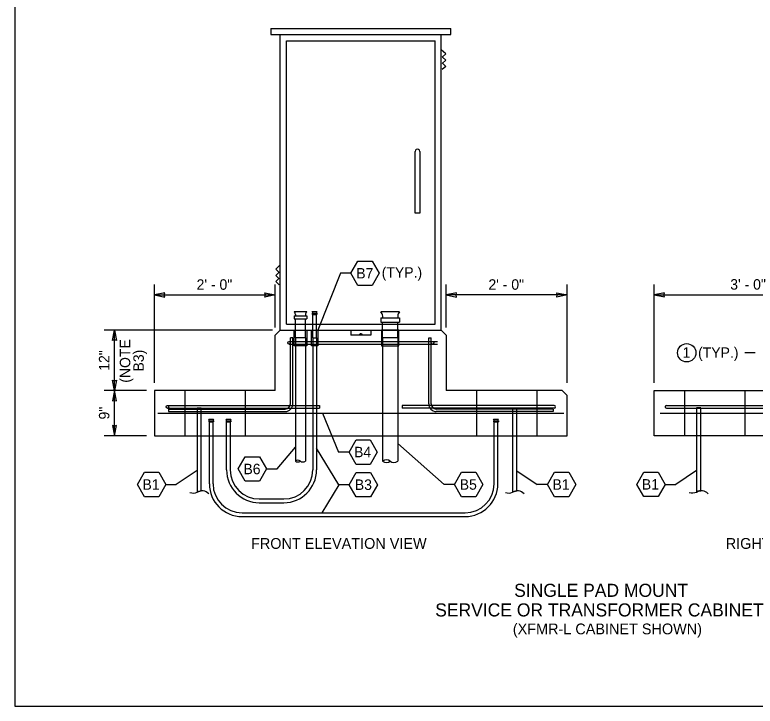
# Model space of a CAD drawing. Extents: x 99862 to 103151, y 100000 to 117076.
# Drawn here: x 99862 to 100994, y 106000 to 107057 of the extents above; entities that cross this region are included whole.
import ezdxf

# ---------------------------------------------------------------- set-up
doc = ezdxf.new("R2010")
doc.units = 0
for name, color, linetype in [('Default', 7, 'Continuous'), ('Level 1', 7, 'Continuous'), ('Level 11', 7, 'Continuous'), ('Level 15', 7, 'Continuous'), ('Level 20', 7, 'Continuous'), ('Level 40', 7, 'Continuous'), ('Level 60', 7, 'Continuous'), ('Level 9', 7, 'Continuous')]:
    doc.layers.add(name, color=color, linetype=linetype)

msp = doc.modelspace()

# ---------------------------------------------------------------- linework, layer by layer
at = {"layer": 'Default'}
for p, q in [((100281.4, 106557.2), (100508.4, 106557.2)), ((100283.4, 106461.6), (100283.4, 106562.9)), ((100287.2, 106562.9), (100283.4, 106562.9)), ((100287.2, 106461.6), (100287.2, 106562.9)), ((100495, 106461.6), (100495, 106562.9)), ((100495, 106562.9), (100498.8, 106562.9)), ((100498.8, 106461.6), (100498.8, 106562.9)), ((100281.4, 106553.3), (100508.4, 106553.3)), ((100095.4, 106459.1), (100327.9, 106459.1)), ((100095.4, 106455.3), (100327.9, 106455.3)), ((100327.9, 106459.1), (100327.9, 106455.3)), ((100454.2, 106459.1), (100454.2, 106455.3)), ((100686.8, 106459.1), (100454.2, 106459.1)), ((100686.8, 106455.3), (100454.2, 106455.3)), ((100858.4, 106459.1), (101091, 106459.1)), ((100858.4, 106455.3), (101091, 106455.3)), ((100096.8, 106453.9), (100096.8, 106450.1)), ((100096.8, 106453.9), (100275.7, 106453.9)), ((100096.8, 106450.1), (100275.7, 106450.1)), ((100685.4, 106453.9), (100506.5, 106453.9)), ((100685.4, 106450.1), (100506.5, 106450.1)), ((100685.4, 106453.9), (100685.4, 106450.1))]:
    msp.add_line(p, q, dxfattribs=at)
for centre, radius in [((100391.1, 106568.2), 1.44), ((100281.4, 106555.2), 1.92), ((100500.7, 106555.2), 1.92), ((100095.4, 106457.2), 1.92)]:
    msp.add_circle(centre, radius, dxfattribs=at)
for centre, radius, start, end in [((100275.7, 106461.6), 11.5, 270, 0), ((100275.7, 106461.6), 7.7, 270, 0), ((100506.5, 106461.6), 11.5, 180, 270), ((100506.5, 106461.6), 7.7, 180, 270), ((100686.8, 106457.2), 1.92, 270, 90), ((100858.4, 106457.2), 1.92, 90, 270.01)]:
    msp.add_arc(centre, radius, start, end, dxfattribs=at)
at = {"layer": 'Level 1'}
for p, q in [((100289.2, 106602.8), (100308.4, 106602.8)), ((100316.9, 106602.8), (100324.1, 106602.8)), ((100421.6, 106602.8), (100450.5, 106602.8)), ((100289.2, 106596.4), (100289.2, 106591.9)), ((100289.2, 106596.4), (100308.4, 106596.4)), ((100289.2, 106591.9), (100308.4, 106591.9)), ((100291.1, 106598.2), (100291.1, 106596.4)), ((100291.1, 106562.6), (100291.1, 106591.9)), ((100306.5, 106598.2), (100306.5, 106596.4)), ((100306.5, 106562.6), (100306.5, 106591.9)), ((100308.4, 106596.4), (100308.4, 106591.9)), ((100316.9, 106600.4), (100316.9, 106598.7)), ((100316.9, 106600.4), (100324.1, 106600.4)), ((100316.9, 106598.7), (100324.1, 106598.7)), ((100317.6, 106601.1), (100317.6, 106600.4)), ((100317.6, 106562.6), (100317.6, 106598.7)), ((100323.4, 106601.1), (100323.4, 106600.4)), ((100323.4, 106562.6), (100323.4, 106598.7)), ((100324.1, 106600.4), (100324.1, 106598.7)), ((100421.6, 106593.3), (100421.6, 106586.5)), ((100421.6, 106593.3), (100450.5, 106593.3)), ((100424.5, 106595.9), (100424.5, 106593.3)), ((100447.6, 106595.9), (100447.6, 106593.3)), ((100450.5, 106593.3), (100450.5, 106586.5)), ((100421.6, 106586.5), (100450.5, 106586.5)), ((100424.5, 106562.6), (100424.5, 106586.5)), ((100447.6, 106562.6), (100447.6, 106586.5)), ((100306.5, 106562.6), (100291.1, 106562.6)), ((100291.1, 106562.6), (100291.1, 106374.3)), ((100306.5, 106562.6), (100306.5, 106374.3)), ((100317.6, 106562.6), (100323.4, 106562.6)), ((100317.6, 106562.6), (100317.6, 106360.7)), ((100323.4, 106562.6), (100323.4, 106360.7)), ((100424.5, 106562.6), (100424.5, 106374.3)), ((100447.6, 106562.6), (100424.5, 106562.6)), ((100447.6, 106562.6), (100447.6, 106374.3)), ((100158.8, 106438.3), (100166, 106438.3)), ((100158.8, 106436), (100158.8, 106434.3)), ((100158.8, 106436), (100166, 106436)), ((100158.8, 106434.3), (100166, 106434.3)), ((100159.5, 106436.6), (100159.5, 106436)), ((100159.5, 106339.5), (100159.5, 106434.3)), ((100165.3, 106436.6), (100165.3, 106436)), ((100165.3, 106339.5), (100165.3, 106434.3)), ((100166, 106436), (100166, 106434.3)), ((100185.2, 106438.3), (100192.4, 106438.3)), ((100185.2, 106436), (100185.2, 106434.3)), ((100185.2, 106436), (100192.4, 106436)), ((100185.2, 106434.3), (100192.4, 106434.3)), ((100185.9, 106436.6), (100185.9, 106436)), ((100185.9, 106360.7), (100185.9, 106434.3)), ((100191.7, 106436.6), (100191.7, 106436)), ((100191.7, 106360.7), (100191.7, 106434.3)), ((100192.4, 106436), (100192.4, 106434.3)), ((100594.3, 106438.3), (100601.5, 106438.3)), ((100594.3, 106436), (100594.3, 106434.3)), ((100594.3, 106436), (100601.5, 106436)), ((100594.3, 106434.3), (100601.5, 106434.3)), ((100595, 106436.6), (100595, 106436)), ((100595, 106338), (100595, 106434.3)), ((100600.7, 106436.6), (100600.7, 106436)), ((100600.7, 106337.9), (100600.7, 106434.3)), ((100601.5, 106436), (100601.5, 106434.3)), ((100235.9, 106316.4), (100273.4, 106316.4)), ((100235.9, 106310.7), (100273.4, 106310.7)), ((100209.5, 106295.3), (100550.7, 106295.3)), ((100209.5, 106289.5), (100550.7, 106289.5))]:
    msp.add_line(p, q, dxfattribs=at)
for points in [[(99862, 105999.5), (103151, 105999.5), (103151, 108075.5), (99862, 108075.5)], [(100308.4, 106550.6), (100289.2, 106550.6), (100289.2, 106574.5), (100308.4, 106574.5)], [(100315.7, 106574.5), (100325.3, 106574.5), (100325.3, 106550.6), (100315.7, 106550.6)], [(100422.6, 106550.6), (100449.5, 106550.6), (100449.5, 106574.5), (100422.6, 106574.5)], [(100141, 106455.3), (100141, 106326.8), (100143.2, 106327.9), (100145.2, 106328.5), (100147.2, 106328.8), (100147.2, 106455.3)], [(100623.3, 106455.3), (100623.3, 106326.8), (100625.5, 106327.9), (100627.5, 106328.5), (100629.5, 106328.8), (100629.6, 106455.3)], [(100904.7, 106455.5), (100904.7, 106327), (100906.9, 106328.1), (100908.9, 106328.7), (100910.9, 106329), (100910.9, 106455.5)]]:
    msp.add_lwpolyline(points, close=True, dxfattribs=at)
for centre, radius, start, end in [((100284.8, 106598.2), 6.32, 0, 45.9402), ((100312.8, 106598.2), 6.32, 134.0598, 180), ((100315.3, 106601.1), 2.37, 0, 45.9402), ((100325.8, 106601.1), 2.37, 134.0598, 180), ((100415.1, 106595.9), 9.47, 0, 45.9402), ((100457.1, 106595.9), 9.47, 134.0598, 180), ((100157.1, 106436.6), 2.37, 0, 45.9402), ((100167.7, 106436.6), 2.37, 134.0598, 180), ((100183.5, 106436.6), 2.37, 0, 45.9402), ((100194, 106436.6), 2.37, 134.0598, 180), ((100592.6, 106436.6), 2.37, 0, 45.9402), ((100603.1, 106436.6), 2.37, 134.0598, 180), ((100430.3, 106367.2), 9.14, 50.8329, 129.1671), ((100294.9, 106369.6), 6.09, 50.8329, 129.1671), ((100294.9, 106379), 6.09, 230.8329, 309.1671), ((100302.6, 106379), 6.09, 230.8329, 309.1671), ((100430.3, 106381.4), 9.14, 230.8329, 309.1671), ((100441.8, 106381.4), 9.14, 230.8329, 309.1671), ((100235.9, 106360.7), 50, 180, 270), ((100235.9, 106360.7), 44.3, 180, 270), ((100273.4, 106360.7), 44.3, 270, 0), ((100273.4, 106360.7), 50, 270, 0), ((100209.5, 106339.5), 50, 180, 270), ((100209.5, 106339.5), 44.3, 180, 270), ((100550.7, 106339.5), 44.3, 270, 0), ((100550.7, 106339.5), 50, 270, 0), ((100134.6, 106340), 14.6, 250.7571, 295.3506), ((100148.2, 106314.7), 14.1, 42.3778, 121.1813), ((100617, 106340), 14.6, 250.7571, 295.3506), ((100630.5, 106314.7), 14.1, 42.3778, 121.1813), ((100898.3, 106340.2), 14.6, 250.7571, 295.3506), ((100911.9, 106314.9), 14.1, 42.3778, 121.1813)]:
    msp.add_arc(centre, radius, start, end, dxfattribs=at)
at = {"layer": 'Level 11'}
for p, q in [((100375.7, 106574.5), (100375.7, 106566.8)), ((100406.5, 106574.5), (100406.5, 106566.8)), ((100406.5, 106566.8), (100375.7, 106566.8)), ((100121.8, 106482.1), (100121.8, 106412.9)), ((100214.1, 106482.1), (100214.1, 106412.9)), ((100568.1, 106482.1), (100568.1, 106412.9)), ((100660.4, 106482.1), (100660.4, 106412.9)), ((100885.9, 106482.3), (100885.9, 106413.1)), ((100978.3, 106482.3), (100978.3, 106413.1))]:
    msp.add_line(p, q, dxfattribs=at)
for points in [[(100260.3, 106482.1), (100260.3, 106566.8), (100268, 106574.5)], [(100268, 106574.5), (100514.2, 106574.5)], [(100514.2, 106574.5), (100521.9, 106566.8), (100521.9, 106482.1)], [(100075.6, 106482.1), (100075.6, 106412.9)], [(100260.3, 106482.1), (100075.6, 106482.1)], [(100698.9, 106482.1), (100521.9, 106482.1)], [(100706.6, 106412.9), (100706.6, 106474.4), (100698.9, 106482.1)], [(100839.7, 106482.3), (101128.3, 106482.3)], [(100839.7, 106413.1), (100839.7, 106482.3)], [(100075.6, 106412.9), (100706.6, 106412.9)], [(101363, 106413.1), (100839.7, 106413.1)]]:
    msp.add_lwpolyline(points, dxfattribs=at)
at = {"layer": 'Level 15'}
for p, q in [((100359.9, 106661.5), (100325.3, 106574.5)), ((100375.9, 106661.5), (100359.9, 106661.5)), ((100075.6, 106494.1), (100075.6, 106644.3)), ((100260.3, 106578.8), (100260.3, 106644.3)), ((100521.9, 106578.8), (100521.9, 106644.3)), ((100706.6, 106494.1), (100706.6, 106644.3)), ((100839.7, 106494.1), (100839.7, 106644.5)), ((100075.6, 106628.3), (100260.3, 106628.3)), ((100706.6, 106628.3), (100521.9, 106628.3)), ((100839.7, 106628.5), (101128.3, 106628.5)), ((100256, 106574.5), (99998.6, 106574.5)), ((100014.6, 106482.1), (100014.6, 106574.5)), ((100978.2, 106540.2), (100994.2, 106540.2)), ((100063.6, 106482.1), (99998.6, 106482.1)), ((100014.6, 106412.9), (100014.6, 106482.1)), ((100332.5, 106447.4), (100357.1, 106388)), ((100063.6, 106412.9), (99998.6, 106412.9)), ((100518.5, 106338.5), (100447.6, 106401)), ((100263, 106362.2), (100291.1, 106395.6)), ((100357.4, 106338.2), (100323.4, 106394.2)), ((100373.1, 106388), (100357.1, 106388)), ((100141, 106359.9), (100109, 106338.5)), ((100247, 106362.2), (100263, 106362.2)), ((100629.5, 106359.4), (100660.7, 106338.5)), ((100904.7, 106360.1), (100872.7, 106338.7)), ((100093, 106338.5), (100109, 106338.5)), ((100357.4, 106338.2), (100331.5, 106295.3)), ((100373.4, 106338.2), (100357.4, 106338.2)), ((100534.5, 106338.5), (100518.5, 106338.5)), ((100676.7, 106338.5), (100660.7, 106338.5)), ((100856.7, 106338.7), (100872.7, 106338.7))]:
    msp.add_line(p, q, dxfattribs=at)
for points in [[(100075.6, 106628.3), (100091.3, 106625.2), (100090.6, 106628.3), (100091.3, 106631.4)], [(100260.3, 106628.3), (100244.5, 106625.2), (100245.3, 106628.3), (100244.5, 106631.4)], [(100521.9, 106628.3), (100537.6, 106625.2), (100536.9, 106628.3), (100537.6, 106631.4)], [(100706.6, 106628.3), (100690.9, 106625.2), (100691.6, 106628.3), (100690.9, 106631.4)], [(100839.7, 106628.5), (100855.5, 106625.4), (100854.7, 106628.5), (100855.5, 106631.6)], [(100014.6, 106574.5), (100017.7, 106558.8), (100014.6, 106559.5), (100011.5, 106558.8)], [(100014.6, 106482.1), (100011.5, 106497.9), (100014.6, 106497.1), (100017.7, 106497.9)], [(100014.6, 106482.1), (100011.5, 106466.4), (100014.6, 106467.1), (100017.7, 106466.4)], [(100014.6, 106412.9), (100017.7, 106428.6), (100014.6, 106427.9), (100011.5, 106428.6)]]:
    msp.add_lwpolyline(points, close=True, dxfattribs=at)
at = {"layer": 'Level 20'}
for points in [[(100375.9, 106661.5), (100386.7, 106680.2), (100408.3, 106680.2), (100419.1, 106661.5), (100408.3, 106642.7), (100386.7, 106642.7), (100375.9, 106661.5)], [(100373.1, 106388), (100384, 106406.8), (100405.6, 106406.8), (100416.4, 106388), (100405.6, 106369.3), (100384, 106369.3), (100373.1, 106388)], [(100203.7, 106362.2), (100214.5, 106380.9), (100236.2, 106380.9), (100247, 106362.2), (100236.2, 106343.4), (100214.5, 106343.4), (100203.7, 106362.2)], [(100049.7, 106338.5), (100060.5, 106357.2), (100082.2, 106357.2), (100093, 106338.5), (100082.2, 106319.7), (100060.5, 106319.7), (100049.7, 106338.5)], [(100373.4, 106338.2), (100384.2, 106356.9), (100405.9, 106356.9), (100416.7, 106338.2), (100405.9, 106319.4), (100384.2, 106319.4), (100373.4, 106338.2)], [(100534.5, 106338.5), (100545.3, 106357.2), (100567, 106357.2), (100577.8, 106338.5), (100567, 106319.7), (100545.3, 106319.7), (100534.5, 106338.5)], [(100676.7, 106338.5), (100687.5, 106357.2), (100709.2, 106357.2), (100720, 106338.5), (100709.2, 106319.7), (100687.5, 106319.7), (100676.7, 106338.5)], [(100813.4, 106338.7), (100824.2, 106357.4), (100845.9, 106357.4), (100856.7, 106338.7), (100845.9, 106319.9), (100824.2, 106319.9), (100813.4, 106338.7)]]:
    msp.add_lwpolyline(points, dxfattribs=at)
msp.add_circle((100889.6, 106539.9), 14, dxfattribs=at)
at = {"layer": 'Level 40'}
for p, q in [((100080.7, 106447.5), (100701.5, 106447.5)), ((100848.7, 106447.7), (101354, 106447.7))]:
    msp.add_line(p, q, dxfattribs=at)
at = {"layer": 'Level 60'}
msp.add_line((99862, 105999.5), (99862, 105999.5), dxfattribs=at)
at = {"layer": 'Level 9'}
for p, q in [((100253.5, 107036), (100528.6, 107036)), ((100253.5, 107036), (100253.5, 107026.5)), ((100528.6, 107026.5), (100528.6, 107036)), ((100253.5, 107026.5), (100268, 107026.5)), ((100268, 106574.5), (100268, 107026.5)), ((100268, 107026.5), (100528.6, 107026.5)), ((100514.2, 106574.5), (100514.2, 107026.5)), ((100277.6, 106583.9), (100277.6, 107017.1)), ((100277.6, 107017.1), (100504.6, 107017.1)), ((100504.6, 106583.9), (100504.6, 107017.1)), ((100521, 106996.8), (100514.2, 107003.4)), ((100521, 106996.8), (100515.8, 106991.8)), ((100521, 106987.3), (100515.8, 106982.3)), ((100521, 106987.3), (100516.1, 106992.1)), ((100521, 106977.9), (100515.8, 106972.9)), ((100521, 106977.9), (100516.1, 106982.6)), ((100474.1, 106843.2), (100474.1, 106847.9)), ((100474.1, 106753.6), (100474.1, 106843.2)), ((100481.3, 106847.9), (100481.3, 106843.2)), ((100481.3, 106843.2), (100481.3, 106753.6)), ((100481.3, 106753.6), (100474.1, 106753.6)), ((100261.2, 106667.6), (100268, 106674.2)), ((100261.2, 106667.6), (100266.3, 106662.6)), ((100261.2, 106658.1), (100266, 106662.8)), ((100261.2, 106658.1), (100266.3, 106653.1)), ((100261.2, 106648.7), (100266, 106653.4)), ((100261.2, 106648.7), (100266.3, 106643.7)), ((100277.6, 106583.9), (100504.6, 106583.9))]:
    msp.add_line(p, q, dxfattribs=at)
msp.add_ellipse((100477.7, 106847.9), major_axis=(3.61, 0), ratio=0.979592, start_param=0, end_param=3.141593, dxfattribs=at)

# ---------------------------------------------------------------- texts
at = {"layer": 'Level 20'}
for s, height, p in [('(TYP.)', 16, (100423.1, 106654.8)), ('B7', 16, (100384.2, 106653.5)), ('2\' - 0"', 16, (100140, 106636.3)), ('2\' - 0"', 16, (100586.3, 106636.3)), ('3\' - 0"', 16, (100956.1, 106636.5)), ('1  (TYP.)', 16, (100883.1, 106532.2)), ('B4', 16, (100380.8, 106380.1)), ('B6', 16, (100211.6, 106354.2)), ('B1', 16, (100057.2, 106330.5)), ('B3', 16, (100382, 106330.2)), ('B5', 16, (100542.4, 106330.5)), ('B1', 16, (100684.2, 106330.5)), ('B1', 16, (100820.9, 106330.7)), ('FRONT ELEVATION VIEW', 16.5, (100223.3, 106240.1)), ('RIGHT SIDE ELEVATION VIEW', 16.5, (100949.2, 106240.1)), ('SINGLE PAD MOUNT', 20, (100625.6, 106166.7)), ('SERVICE OR TRANSFORMER CABINET', 20, (100504.9, 106136.7)), ('(XFMR-L CABINET SHOWN)', 16.5, (100623.6, 106109.4))]:
    msp.add_text(s, height=height, dxfattribs=at).set_placement(p)
for s, p in [('(NOTE', (100038.6, 106494.1)), ('12"', (100006.6, 106512.4)), ('B3)', (100059.3, 106511.3)), ('9"', (100006.6, 106437.9))]:
    msp.add_text(s, height=16, rotation=90, dxfattribs=at).set_placement(p)

doc.saveas('drawing.dxf')
